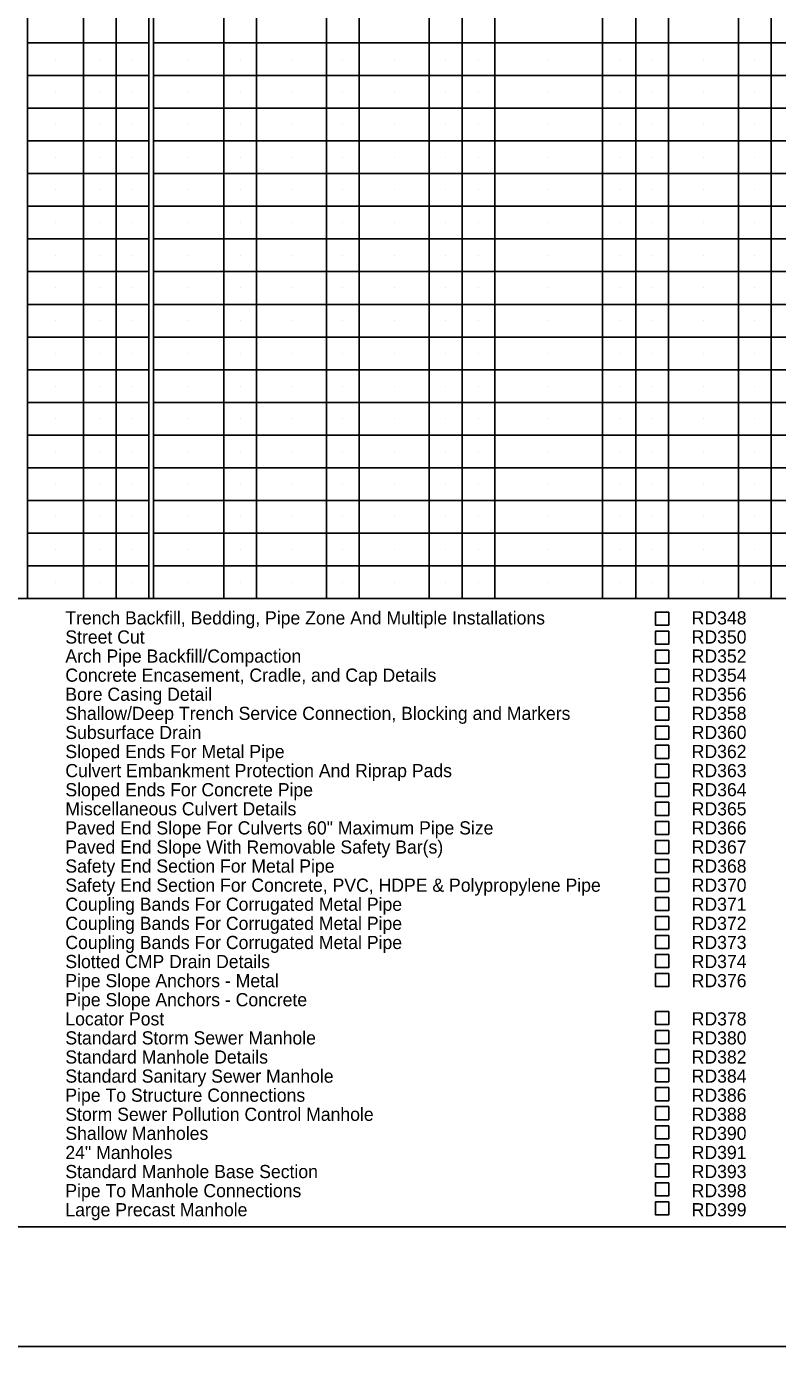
# Model space of a CAD drawing. Extents: x 0 to 1.42, y 0 to 0.92.
# Drawn here: x 0.5109 to 0.7723, y 0 to 0.4596 of the extents above; entities that cross this region are included whole.
import ezdxf

# ---------------------------------------------------------------- set-up
doc = ezdxf.new("R2010")
doc.units = 0
for name, color, linetype in [('#plot_shape', 7, 'Continuous'), ('P_ODOT_PLAN_Border', 7, 'Continuous'), ('P_ODOT_PLAN_General', 7, 'Continuous'), ('P_RDWY_PLAN_NotesTx', 7, 'Continuous')]:
    doc.layers.add(name, color=color, linetype=linetype)

msp = doc.modelspace()

# ---------------------------------------------------------------- linework, layer by layer
at = {"layer": '#plot_shape'}
msp.add_lwpolyline([(0, 0), (1.41667, 0), (1.41667, 0.91667), (0, 0.91667)], close=True, dxfattribs=at)
at = {"layer": 'P_ODOT_PLAN_Border'}
msp.add_lwpolyline([(0.0625, 0.04167), (1.39583, 0.04167), (1.39583, 0.875), (0.0625, 0.875)], close=True, dxfattribs=at)
at = {"layer": 'P_ODOT_PLAN_General'}
for p, q in [((0.51128, 0.26037), (0.51128, 0.875)), ((0.55355, 0.26037), (0.55355, 0.875)), ((0.55518, 0.26037), (0.55518, 0.875)), ((0.73435, 0.26037), (0.73435, 0.85305)), ((0.54217, 0.26037), (0.54217, 0.84248)), ((0.67388, 0.26037), (0.67388, 0.83191)), ((0.59095, 0.26037), (0.59095, 0.82134)), ((0.62672, 0.26037), (0.62672, 0.82134)), ((0.71138, 0.26037), (0.71138, 0.82134)), ((0.72297, 0.26037), (0.72297, 0.82134)), ((0.77012, 0.26037), (0.77012, 0.82134)), ((0.57957, 0.26037), (0.57957, 0.81159)), ((0.61534, 0.26037), (0.61534, 0.81159)), ((0.65111, 0.26037), (0.65111, 0.81159)), ((0.6625, 0.26037), (0.6625, 0.81159)), ((0.75874, 0.26037), (0.75874, 0.81159)), ((0.53079, 0.26037), (0.53079, 0.76118)), ((0.55355, 0.45387), (0.51128, 0.45387)), ((1.06002, 0.45387), (0.55518, 0.45387)), ((0.52103, 0.44818), (0.52103, 0.44818)), ((0.53648, 0.44818), (0.53648, 0.44818)), ((0.54786, 0.44818), (0.54786, 0.44818)), ((0.56737, 0.44818), (0.56737, 0.44818)), ((0.58526, 0.44818), (0.58526, 0.44818)), ((0.60315, 0.44818), (0.60315, 0.44818)), ((0.62103, 0.44818), (0.62103, 0.44818)), ((0.63892, 0.44818), (0.63892, 0.44818)), ((0.6568, 0.44818), (0.6568, 0.44818)), ((0.66819, 0.44818), (0.66819, 0.44818)), ((0.69263, 0.44818), (0.69263, 0.44818)), ((0.71728, 0.44818), (0.71728, 0.44818)), ((0.72866, 0.44818), (0.72866, 0.44818)), ((0.74654, 0.44818), (0.74654, 0.44818)), ((0.76443, 0.44818), (0.76443, 0.44818)), ((0.55355, 0.44248), (0.51128, 0.44248)), ((1.06002, 0.44248), (0.55518, 0.44248)), ((0.52103, 0.43679), (0.52103, 0.43679)), ((0.53648, 0.43679), (0.53648, 0.43679)), ((0.54786, 0.43679), (0.54786, 0.43679)), ((0.56737, 0.43679), (0.56737, 0.43679)), ((0.58526, 0.43679), (0.58526, 0.43679)), ((0.60315, 0.43679), (0.60315, 0.43679)), ((0.62103, 0.43679), (0.62103, 0.43679)), ((0.63892, 0.43679), (0.63892, 0.43679)), ((0.6568, 0.43679), (0.6568, 0.43679)), ((0.66819, 0.43679), (0.66819, 0.43679)), ((0.69263, 0.43679), (0.69263, 0.43679)), ((0.71728, 0.43679), (0.71728, 0.43679)), ((0.72866, 0.43679), (0.72866, 0.43679)), ((0.74654, 0.43679), (0.74654, 0.43679)), ((0.76443, 0.43679), (0.76443, 0.43679)), ((0.55355, 0.4311), (0.51128, 0.4311)), ((1.06002, 0.4311), (0.55518, 0.4311)), ((0.52103, 0.42541), (0.52103, 0.42541)), ((0.53648, 0.42541), (0.53648, 0.42541)), ((0.54786, 0.42541), (0.54786, 0.42541)), ((0.56737, 0.42541), (0.56737, 0.42541)), ((0.58526, 0.42541), (0.58526, 0.42541)), ((0.60315, 0.42541), (0.60315, 0.42541)), ((0.62103, 0.42541), (0.62103, 0.42541)), ((0.63892, 0.42541), (0.63892, 0.42541)), ((0.6568, 0.42541), (0.6568, 0.42541)), ((0.66819, 0.42541), (0.66819, 0.42541)), ((0.69263, 0.42541), (0.69263, 0.42541)), ((0.71728, 0.42541), (0.71728, 0.42541)), ((0.72866, 0.42541), (0.72866, 0.42541)), ((0.74654, 0.42541), (0.74654, 0.42541)), ((0.76443, 0.42541), (0.76443, 0.42541)), ((0.55355, 0.41972), (0.51128, 0.41972)), ((1.06002, 0.41972), (0.55518, 0.41972)), ((0.52103, 0.41403), (0.52103, 0.41403)), ((0.53648, 0.41403), (0.53648, 0.41403)), ((0.54786, 0.41403), (0.54786, 0.41403)), ((0.56737, 0.41403), (0.56737, 0.41403)), ((0.58526, 0.41403), (0.58526, 0.41403)), ((0.60315, 0.41403), (0.60315, 0.41403)), ((0.62103, 0.41403), (0.62103, 0.41403)), ((0.63892, 0.41403), (0.63892, 0.41403)), ((0.6568, 0.41403), (0.6568, 0.41403)), ((0.66819, 0.41403), (0.66819, 0.41403)), ((0.69263, 0.41403), (0.69263, 0.41403)), ((0.71728, 0.41403), (0.71728, 0.41403)), ((0.72866, 0.41403), (0.72866, 0.41403)), ((0.74654, 0.41403), (0.74654, 0.41403)), ((0.76443, 0.41403), (0.76443, 0.41403)), ((0.55355, 0.40834), (0.51128, 0.40834)), ((1.06002, 0.40834), (0.55518, 0.40834)), ((0.52103, 0.40265), (0.52103, 0.40265)), ((0.53648, 0.40265), (0.53648, 0.40265)), ((0.54786, 0.40265), (0.54786, 0.40265)), ((0.56737, 0.40265), (0.56737, 0.40265)), ((0.58526, 0.40265), (0.58526, 0.40265)), ((0.60315, 0.40265), (0.60315, 0.40265)), ((0.62103, 0.40265), (0.62103, 0.40265)), ((0.63892, 0.40265), (0.63892, 0.40265)), ((0.6568, 0.40265), (0.6568, 0.40265)), ((0.66819, 0.40265), (0.66819, 0.40265)), ((0.69263, 0.40265), (0.69263, 0.40265)), ((0.71728, 0.40265), (0.71728, 0.40265)), ((0.72866, 0.40265), (0.72866, 0.40265)), ((0.74654, 0.40265), (0.74654, 0.40265)), ((0.76443, 0.40265), (0.76443, 0.40265)), ((0.55355, 0.39696), (0.51128, 0.39696)), ((1.06002, 0.39696), (0.55518, 0.39696)), ((0.52103, 0.39127), (0.52103, 0.39127)), ((0.53648, 0.39127), (0.53648, 0.39127)), ((0.54786, 0.39127), (0.54786, 0.39127)), ((0.56737, 0.39127), (0.56737, 0.39127)), ((0.58526, 0.39127), (0.58526, 0.39127)), ((0.60315, 0.39127), (0.60315, 0.39127)), ((0.62103, 0.39127), (0.62103, 0.39127)), ((0.63892, 0.39127), (0.63892, 0.39127)), ((0.6568, 0.39127), (0.6568, 0.39127)), ((0.66819, 0.39127), (0.66819, 0.39127)), ((0.69263, 0.39127), (0.69263, 0.39127)), ((0.71728, 0.39127), (0.71728, 0.39127)), ((0.72866, 0.39127), (0.72866, 0.39127)), ((0.74654, 0.39127), (0.74654, 0.39127)), ((0.76443, 0.39127), (0.76443, 0.39127)), ((0.55355, 0.38557), (0.51128, 0.38557)), ((1.06002, 0.38557), (0.55518, 0.38557)), ((0.52103, 0.37988), (0.52103, 0.37988)), ((0.53648, 0.37988), (0.53648, 0.37988)), ((0.54786, 0.37988), (0.54786, 0.37988)), ((0.56737, 0.37988), (0.56737, 0.37988)), ((0.58526, 0.37988), (0.58526, 0.37988)), ((0.60315, 0.37988), (0.60315, 0.37988)), ((0.62103, 0.37988), (0.62103, 0.37988)), ((0.63892, 0.37988), (0.63892, 0.37988)), ((0.6568, 0.37988), (0.6568, 0.37988)), ((0.66819, 0.37988), (0.66819, 0.37988)), ((0.69263, 0.37988), (0.69263, 0.37988)), ((0.71728, 0.37988), (0.71728, 0.37988)), ((0.72866, 0.37988), (0.72866, 0.37988)), ((0.74654, 0.37988), (0.74654, 0.37988)), ((0.76443, 0.37988), (0.76443, 0.37988)), ((0.55355, 0.37419), (0.51128, 0.37419)), ((1.06002, 0.37419), (0.55518, 0.37419)), ((0.52103, 0.3685), (0.52103, 0.3685)), ((0.53648, 0.3685), (0.53648, 0.3685)), ((0.54786, 0.3685), (0.54786, 0.3685)), ((0.56737, 0.3685), (0.56737, 0.3685)), ((0.58526, 0.3685), (0.58526, 0.3685)), ((0.60315, 0.3685), (0.60315, 0.3685)), ((0.62103, 0.3685), (0.62103, 0.3685)), ((0.63892, 0.3685), (0.63892, 0.3685)), ((0.6568, 0.3685), (0.6568, 0.3685)), ((0.66819, 0.3685), (0.66819, 0.3685)), ((0.69263, 0.3685), (0.69263, 0.3685)), ((0.71728, 0.3685), (0.71728, 0.3685)), ((0.72866, 0.3685), (0.72866, 0.3685)), ((0.74654, 0.3685), (0.74654, 0.3685)), ((0.76443, 0.3685), (0.76443, 0.3685)), ((0.55355, 0.36281), (0.51128, 0.36281)), ((1.06002, 0.36281), (0.55518, 0.36281)), ((0.52103, 0.35712), (0.52103, 0.35712)), ((0.53648, 0.35712), (0.53648, 0.35712)), ((0.54786, 0.35712), (0.54786, 0.35712)), ((0.56737, 0.35712), (0.56737, 0.35712)), ((0.58526, 0.35712), (0.58526, 0.35712)), ((0.60315, 0.35712), (0.60315, 0.35712)), ((0.62103, 0.35712), (0.62103, 0.35712)), ((0.63892, 0.35712), (0.63892, 0.35712)), ((0.6568, 0.35712), (0.6568, 0.35712)), ((0.66819, 0.35712), (0.66819, 0.35712)), ((0.69263, 0.35712), (0.69263, 0.35712)), ((0.71728, 0.35712), (0.71728, 0.35712)), ((0.72866, 0.35712), (0.72866, 0.35712)), ((0.74654, 0.35712), (0.74654, 0.35712)), ((0.76443, 0.35712), (0.76443, 0.35712)), ((0.55355, 0.35143), (0.51128, 0.35143)), ((1.06002, 0.35143), (0.55518, 0.35143)), ((0.52103, 0.34574), (0.52103, 0.34574)), ((0.53648, 0.34574), (0.53648, 0.34574)), ((0.54786, 0.34574), (0.54786, 0.34574)), ((0.56737, 0.34574), (0.56737, 0.34574)), ((0.58526, 0.34574), (0.58526, 0.34574)), ((0.60315, 0.34574), (0.60315, 0.34574)), ((0.62103, 0.34574), (0.62103, 0.34574)), ((0.63892, 0.34574), (0.63892, 0.34574)), ((0.6568, 0.34574), (0.6568, 0.34574)), ((0.66819, 0.34574), (0.66819, 0.34574)), ((0.69263, 0.34574), (0.69263, 0.34574)), ((0.71728, 0.34574), (0.71728, 0.34574)), ((0.72866, 0.34574), (0.72866, 0.34574)), ((0.74654, 0.34574), (0.74654, 0.34574)), ((0.76443, 0.34574), (0.76443, 0.34574)), ((0.55355, 0.34005), (0.51128, 0.34005)), ((1.06002, 0.34005), (0.55518, 0.34005)), ((0.52103, 0.33436), (0.52103, 0.33436)), ((0.53648, 0.33436), (0.53648, 0.33436)), ((0.54786, 0.33436), (0.54786, 0.33436)), ((0.56737, 0.33436), (0.56737, 0.33436)), ((0.58526, 0.33436), (0.58526, 0.33436)), ((0.60315, 0.33436), (0.60315, 0.33436)), ((0.62103, 0.33436), (0.62103, 0.33436)), ((0.63892, 0.33436), (0.63892, 0.33436)), ((0.6568, 0.33436), (0.6568, 0.33436)), ((0.66819, 0.33436), (0.66819, 0.33436)), ((0.69263, 0.33436), (0.69263, 0.33436)), ((0.71728, 0.33436), (0.71728, 0.33436)), ((0.72866, 0.33436), (0.72866, 0.33436)), ((0.74654, 0.33436), (0.74654, 0.33436)), ((0.76443, 0.33436), (0.76443, 0.33436)), ((0.55355, 0.32866), (0.51128, 0.32866)), ((1.06002, 0.32866), (0.55518, 0.32866)), ((0.52103, 0.32297), (0.52103, 0.32297)), ((0.53648, 0.32297), (0.53648, 0.32297)), ((0.54786, 0.32297), (0.54786, 0.32297)), ((0.56737, 0.32297), (0.56737, 0.32297)), ((0.58526, 0.32297), (0.58526, 0.32297)), ((0.60315, 0.32297), (0.60315, 0.32297)), ((0.62103, 0.32297), (0.62103, 0.32297)), ((0.63892, 0.32297), (0.63892, 0.32297)), ((0.6568, 0.32297), (0.6568, 0.32297)), ((0.66819, 0.32297), (0.66819, 0.32297)), ((0.69263, 0.32297), (0.69263, 0.32297)), ((0.71728, 0.32297), (0.71728, 0.32297)), ((0.72866, 0.32297), (0.72866, 0.32297)), ((0.74654, 0.32297), (0.74654, 0.32297)), ((0.76443, 0.32297), (0.76443, 0.32297)), ((0.55355, 0.31728), (0.51128, 0.31728)), ((1.06002, 0.31728), (0.55518, 0.31728)), ((0.52103, 0.31159), (0.52103, 0.31159)), ((0.53648, 0.31159), (0.53648, 0.31159)), ((0.54786, 0.31159), (0.54786, 0.31159)), ((0.56737, 0.31159), (0.56737, 0.31159)), ((0.58526, 0.31159), (0.58526, 0.31159)), ((0.60315, 0.31159), (0.60315, 0.31159)), ((0.62103, 0.31159), (0.62103, 0.31159)), ((0.63892, 0.31159), (0.63892, 0.31159)), ((0.6568, 0.31159), (0.6568, 0.31159)), ((0.66819, 0.31159), (0.66819, 0.31159)), ((0.69263, 0.31159), (0.69263, 0.31159)), ((0.71728, 0.31159), (0.71728, 0.31159)), ((0.72866, 0.31159), (0.72866, 0.31159)), ((0.74654, 0.31159), (0.74654, 0.31159)), ((0.76443, 0.31159), (0.76443, 0.31159)), ((0.55355, 0.3059), (0.51128, 0.3059)), ((1.06002, 0.3059), (0.55518, 0.3059)), ((0.52103, 0.30021), (0.52103, 0.30021)), ((0.53648, 0.30021), (0.53648, 0.30021)), ((0.54786, 0.30021), (0.54786, 0.30021)), ((0.56737, 0.30021), (0.56737, 0.30021)), ((0.58526, 0.30021), (0.58526, 0.30021)), ((0.60315, 0.30021), (0.60315, 0.30021)), ((0.62103, 0.30021), (0.62103, 0.30021)), ((0.63892, 0.30021), (0.63892, 0.30021)), ((0.6568, 0.30021), (0.6568, 0.30021)), ((0.66819, 0.30021), (0.66819, 0.30021)), ((0.69263, 0.30021), (0.69263, 0.30021)), ((0.71728, 0.30021), (0.71728, 0.30021)), ((0.72866, 0.30021), (0.72866, 0.30021)), ((0.74654, 0.30021), (0.74654, 0.30021)), ((0.76443, 0.30021), (0.76443, 0.30021)), ((0.55355, 0.29452), (0.51128, 0.29452)), ((1.06002, 0.29452), (0.55518, 0.29452)), ((0.52103, 0.28883), (0.52103, 0.28883)), ((0.53648, 0.28883), (0.53648, 0.28883)), ((0.54786, 0.28883), (0.54786, 0.28883)), ((0.56737, 0.28883), (0.56737, 0.28883)), ((0.58526, 0.28883), (0.58526, 0.28883)), ((0.60315, 0.28883), (0.60315, 0.28883)), ((0.62103, 0.28883), (0.62103, 0.28883)), ((0.63892, 0.28883), (0.63892, 0.28883)), ((0.6568, 0.28883), (0.6568, 0.28883)), ((0.66819, 0.28883), (0.66819, 0.28883)), ((0.69263, 0.28883), (0.69263, 0.28883)), ((0.71728, 0.28883), (0.71728, 0.28883)), ((0.72866, 0.28883), (0.72866, 0.28883)), ((0.74654, 0.28883), (0.74654, 0.28883)), ((0.76443, 0.28883), (0.76443, 0.28883)), ((0.55355, 0.28314), (0.51128, 0.28314)), ((1.06002, 0.28314), (0.55518, 0.28314)), ((0.52103, 0.27745), (0.52103, 0.27745)), ((0.53648, 0.27745), (0.53648, 0.27745)), ((0.54786, 0.27745), (0.54786, 0.27745)), ((0.56737, 0.27745), (0.56737, 0.27745)), ((0.58526, 0.27745), (0.58526, 0.27745)), ((0.60315, 0.27745), (0.60315, 0.27745)), ((0.62103, 0.27745), (0.62103, 0.27745)), ((0.63892, 0.27745), (0.63892, 0.27745)), ((0.6568, 0.27745), (0.6568, 0.27745)), ((0.66819, 0.27745), (0.66819, 0.27745)), ((0.69263, 0.27745), (0.69263, 0.27745)), ((0.71728, 0.27745), (0.71728, 0.27745)), ((0.72866, 0.27745), (0.72866, 0.27745)), ((0.74654, 0.27745), (0.74654, 0.27745)), ((0.76443, 0.27745), (0.76443, 0.27745)), ((0.55355, 0.27175), (0.51128, 0.27175)), ((1.06002, 0.27175), (0.55518, 0.27175)), ((0.52103, 0.26606), (0.52103, 0.26606)), ((0.53648, 0.26606), (0.53648, 0.26606)), ((0.54786, 0.26606), (0.54786, 0.26606)), ((0.56737, 0.26606), (0.56737, 0.26606)), ((0.58526, 0.26606), (0.58526, 0.26606)), ((0.60315, 0.26606), (0.60315, 0.26606)), ((0.62103, 0.26606), (0.62103, 0.26606)), ((0.63892, 0.26606), (0.63892, 0.26606)), ((0.6568, 0.26606), (0.6568, 0.26606)), ((0.66819, 0.26606), (0.66819, 0.26606)), ((0.69263, 0.26606), (0.69263, 0.26606)), ((0.71728, 0.26606), (0.71728, 0.26606)), ((0.72866, 0.26606), (0.72866, 0.26606)), ((0.74654, 0.26606), (0.74654, 0.26606)), ((0.76443, 0.26606), (0.76443, 0.26606)), ((1.39582, 0.26037), (0.0625, 0.26037)), ((1.39582, 0.26037), (0.0625, 0.26037))]:
    msp.add_line(p, q, dxfattribs=at)
at = {"layer": 'P_RDWY_PLAN_NotesTx'}
for points in [[(0.73443, 0.25567), (0.72987, 0.25567), (0.72987, 0.25111), (0.73443, 0.25111)], [(0.73443, 0.24905), (0.72987, 0.24905), (0.72987, 0.24449), (0.73443, 0.24449)], [(0.73443, 0.24243), (0.72987, 0.24243), (0.72987, 0.23787), (0.73443, 0.23787)], [(0.73443, 0.23581), (0.72987, 0.23581), (0.72987, 0.23125), (0.73443, 0.23125)], [(0.73443, 0.22919), (0.72987, 0.22919), (0.72987, 0.22463), (0.73443, 0.22463)], [(0.73443, 0.22257), (0.72987, 0.22257), (0.72987, 0.21801), (0.73443, 0.21801)], [(0.73443, 0.21595), (0.72987, 0.21595), (0.72987, 0.21139), (0.73443, 0.21139)], [(0.73443, 0.20933), (0.72987, 0.20933), (0.72987, 0.20477), (0.73443, 0.20477)], [(0.73443, 0.2027), (0.72987, 0.2027), (0.72987, 0.19815), (0.73443, 0.19815)], [(0.73443, 0.19608), (0.72987, 0.19608), (0.72987, 0.19153), (0.73443, 0.19153)], [(0.73443, 0.18946), (0.72987, 0.18946), (0.72987, 0.1849), (0.73443, 0.1849)], [(0.73443, 0.18284), (0.72987, 0.18284), (0.72987, 0.17828), (0.73443, 0.17828)], [(0.73443, 0.17622), (0.72987, 0.17622), (0.72987, 0.17166), (0.73443, 0.17166)], [(0.73443, 0.1696), (0.72987, 0.1696), (0.72987, 0.16504), (0.73443, 0.16504)], [(0.73443, 0.16298), (0.72987, 0.16298), (0.72987, 0.15842), (0.73443, 0.15842)], [(0.73443, 0.15636), (0.72987, 0.15636), (0.72987, 0.1518), (0.73443, 0.1518)], [(0.73443, 0.14974), (0.72987, 0.14974), (0.72987, 0.14518), (0.73443, 0.14518)], [(0.73443, 0.14312), (0.72987, 0.14312), (0.72987, 0.13856), (0.73443, 0.13856)], [(0.73443, 0.13649), (0.72987, 0.13649), (0.72987, 0.13194), (0.73443, 0.13194)], [(0.73443, 0.12987), (0.72987, 0.12987), (0.72987, 0.12531), (0.73443, 0.12531)], [(0.73443, 0.11663), (0.72987, 0.11663), (0.72987, 0.11207), (0.73443, 0.11207)], [(0.73443, 0.11001), (0.72987, 0.11001), (0.72987, 0.10545), (0.73443, 0.10545)], [(0.73443, 0.10339), (0.72987, 0.10339), (0.72987, 0.09883), (0.73443, 0.09883)], [(0.73443, 0.09677), (0.72987, 0.09677), (0.72987, 0.09221), (0.73443, 0.09221)], [(0.73443, 0.09015), (0.72987, 0.09015), (0.72987, 0.08559), (0.73443, 0.08559)], [(0.73443, 0.08353), (0.72987, 0.08353), (0.72987, 0.07897), (0.73443, 0.07897)], [(0.73443, 0.0769), (0.72987, 0.0769), (0.72987, 0.07235), (0.73443, 0.07235)], [(0.73443, 0.07028), (0.72987, 0.07028), (0.72987, 0.06572), (0.73443, 0.06572)], [(0.73443, 0.06366), (0.72987, 0.06366), (0.72987, 0.0591), (0.73443, 0.0591)], [(0.73443, 0.05704), (0.72987, 0.05704), (0.72987, 0.05248), (0.73443, 0.05248)], [(0.73443, 0.05042), (0.72987, 0.05042), (0.72987, 0.04586), (0.73443, 0.04586)]]:
    msp.add_lwpolyline(points, close=True, dxfattribs=at)

# ---------------------------------------------------------------- texts
for s, height, p in [('Trench Backfill, Bedding, Pipe Zone And Multiple Installations', 0.0045833, (0.52445, 0.25137)), ('RD348', 0.004583, (0.74244, 0.25137)), ('Street Cut', 0.004583, (0.52445, 0.24473)), ('RD350', 0.004583, (0.74244, 0.24473)), ('Arch Pipe Backfill/Compaction', 0.0045833, (0.52445, 0.23808)), ('RD352', 0.004583, (0.74244, 0.23808)), ('Concrete Encasement, Cradle, and Cap Details', 0.0045833, (0.52445, 0.23144)), ('RD354', 0.004583, (0.74244, 0.23144)), ('Bore Casing Detail', 0.0045833, (0.52445, 0.22479)), ('RD356', 0.004583, (0.74244, 0.22479)), ('Shallow/Deep Trench Service Connection, Blocking and Markers', 0.0045833, (0.52445, 0.21814)), ('RD358', 0.004583, (0.74244, 0.21814)), ('Subsurface Drain', 0.0045833, (0.52445, 0.2115)), ('RD360', 0.004583, (0.74244, 0.2115)), ('Sloped Ends For Metal Pipe', 0.0045833, (0.52445, 0.20485)), ('RD362', 0.004583, (0.74244, 0.20485)), ('Culvert Embankment Protection And Riprap Pads', 0.0045833, (0.52445, 0.19821)), ('RD363', 0.004583, (0.74244, 0.19821)), ('Sloped Ends For Concrete Pipe', 0.0045833, (0.52445, 0.19156)), ('RD364', 0.004583, (0.74244, 0.19156)), ('Miscellaneous Culvert Details', 0.0045833, (0.52445, 0.18492)), ('RD365', 0.004583, (0.74244, 0.18492)), ('Paved End Slope For Culverts 60" Maximum Pipe Size ', 0.0045833, (0.52445, 0.17827)), ('RD366', 0.004583, (0.74244, 0.17827)), ('Paved End Slope With Removable Safety Bar(s)', 0.0045833, (0.52445, 0.17162)), ('RD367', 0.004583, (0.74244, 0.17162)), ('Safety End Section For Metal Pipe', 0.0045833, (0.52445, 0.16498)), ('RD368', 0.004583, (0.74244, 0.16498)), ('Safety End Section For Concrete, PVC, HDPE & Polypropylene Pipe', 0.0045833, (0.52445, 0.15833)), ('RD370', 0.004583, (0.74244, 0.15833)), ('Coupling Bands For Corrugated Metal Pipe', 0.0045833, (0.52445, 0.15169)), ('RD371', 0.004583, (0.74244, 0.15169)), ('Coupling Bands For Corrugated Metal Pipe', 0.0045833, (0.52445, 0.14504)), ('RD372', 0.004583, (0.74244, 0.14504)), ('Coupling Bands For Corrugated Metal Pipe', 0.0045833, (0.52445, 0.13839)), ('RD373', 0.004583, (0.74244, 0.13839)), ('Slotted CMP Drain Details', 0.0045833, (0.52445, 0.13175)), ('RD374', 0.004583, (0.74244, 0.13175)), ('Pipe Slope Anchors - Metal ', 0.0045833, (0.52445, 0.1251)), ('RD376', 0.004583, (0.74244, 0.1251)), ('Pipe Slope Anchors - Concrete', 0.0045833, (0.52445, 0.11846)), ('Locator Post', 0.0045833, (0.52445, 0.11181)), ('RD378', 0.004583, (0.74244, 0.11181)), ('Standard Storm Sewer Manhole', 0.0045833, (0.52445, 0.10517)), ('RD380', 0.004583, (0.74244, 0.10517)), ('Standard Manhole Details', 0.0045833, (0.52445, 0.09852)), ('RD382', 0.004583, (0.74244, 0.09852)), ('Standard Sanitary Sewer Manhole', 0.0045833, (0.52445, 0.09187)), ('RD384', 0.004583, (0.74244, 0.09187)), ('Pipe To Structure Connections', 0.0045833, (0.52445, 0.08523)), ('RD386', 0.004583, (0.74244, 0.08523)), ('Storm Sewer Pollution Control Manhole', 0.0045833, (0.52445, 0.07858)), ('RD388', 0.004583, (0.74244, 0.07858)), ('Shallow Manholes', 0.0045833, (0.52445, 0.07194)), ('RD390', 0.004583, (0.74244, 0.07194)), ('24" Manholes', 0.0045833, (0.52445, 0.06529)), ('RD391', 0.004583, (0.74244, 0.06529)), ('Standard Manhole Base Section', 0.0045833, (0.52445, 0.05864)), ('RD393', 0.004583, (0.74244, 0.05864)), ('Pipe To Manhole Connections', 0.0045833, (0.52445, 0.052)), ('RD398', 0.004583, (0.74244, 0.052)), ('Large Precast Manhole', 0.0045833, (0.52445, 0.04535)), ('RD399', 0.004583, (0.74244, 0.04535))]:
    msp.add_text(s, height=height, dxfattribs=at).set_placement(p)

doc.saveas('drawing.dxf')
